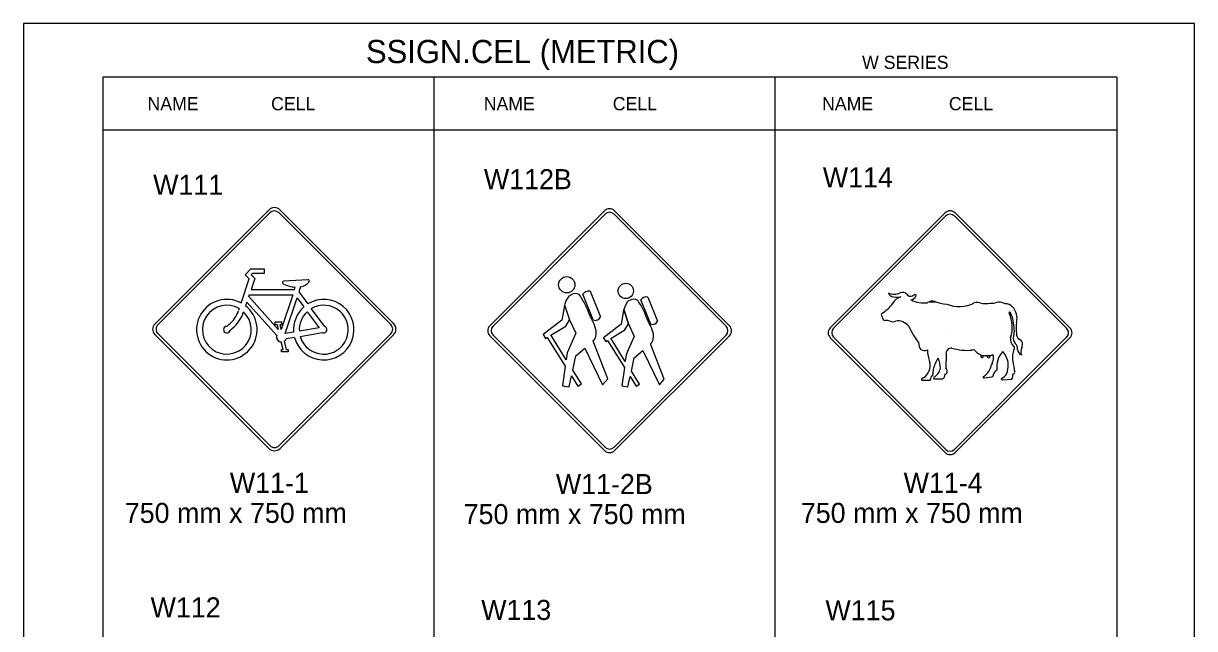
# Model space of a CAD drawing. Extents: x -12 to 6962, y -3756 to 679.
# Drawn here: x 2167.2 to 2342.4, y -112.9 to -22.3 of the extents above; entities that cross this region are included whole.
import ezdxf

# ---------------------------------------------------------------- set-up
doc = ezdxf.new("R2010")
doc.units = 0
for name, color, linetype in [('Level 1', 7, 'Continuous'), ('Level 2', 7, 'Continuous'), ('Level 3', 7, 'Continuous'), ('Level 62', 7, 'Continuous')]:
    doc.layers.add(name, color=color, linetype=linetype)

msp = doc.modelspace()

# ---------------------------------------------------------------- linework, layer by layer
at = {"layer": 'Level 1'}
for p, q in [((2330.8, -30.35), (2179.04, -30.35)), ((2179.04, -30.35), (2179.04, -230.35)), ((2228.56, -30.35), (2228.56, -230.35)), ((2279.62, -30.35), (2279.62, -230.35)), ((2330.8, -30.35), (2330.8, -230.35)), ((2330.8, -38.27), (2179.04, -38.27)), ((2186.83, -67.3), (2203.92, -50.21)), ((2187.31, -67.37), (2204.02, -50.67)), ((2205.44, -50.67), (2222.14, -67.37)), ((2205.54, -50.21), (2222.56, -67.23)), ((2236.95, -67.55), (2254.14, -50.37)), ((2255.63, -50.37), (2272.82, -67.55)), ((2287.91, -67.86), (2305.1, -50.67)), ((2306.59, -50.67), (2323.78, -67.86)), ((2237.45, -67.61), (2254.2, -50.86)), ((2255.57, -50.86), (2272.32, -67.61)), ((2288.41, -67.92), (2305.16, -51.17)), ((2306.53, -51.17), (2323.28, -67.92)), ((2200.33, -59.95), (2201.21, -59.06)), ((2201.21, -59.06), (2203.21, -59.06)), ((2203.21, -59.06), (2203.21, -59.73)), ((2199.74, -64.16), (2200.95, -60.56)), ((2200.95, -60.56), (2200.33, -59.95)), ((2201.78, -60.49), (2201.24, -62.13)), ((2201.5, -59.73), (2201.26, -59.95)), ((2201.26, -59.95), (2201.78, -60.49)), ((2203.21, -59.73), (2201.5, -59.73)), ((2206.14, -60.85), (2209.73, -60.66)), ((2200.88, -63.2), (2200.97, -62.92)), ((2200.97, -62.92), (2207.47, -62.92)), ((2201.24, -62.13), (2207.71, -62.13)), ((2207.47, -62.92), (2205.76, -68.11)), ((2207.71, -62.13), (2207.83, -61.75)), ((2208.63, -61.73), (2208.4, -62.47)), ((2208.4, -62.47), (2209.73, -64.28)), ((2252.43, -66.69), (2250.86, -62.85)), ((2251.96, -62.39), (2253.54, -66.24)), ((2200.59, -64.04), (2200.4, -64.58)), ((2205.07, -69.01), (2200.59, -64.04)), ((2205.3, -68.13), (2200.88, -63.2)), ((2206.35, -68.72), (2208.11, -63.37)), ((2208.11, -63.37), (2209.13, -64.73)), ((2248.14, -64.52), (2247.74, -66.73)), ((2248.16, -64.41), (2248.89, -66.65)), ((2261.04, -67.3), (2259.55, -63.68)), ((2260.59, -63.26), (2262.07, -66.88)), ((2302.77, -63.96), (2303.59, -63.96)), ((2199.47, -64.99), (2199.36, -65.3)), ((2200.07, -65.56), (2200.12, -65.46)), ((2209.63, -65.46), (2211.44, -67.87)), ((2212.25, -67.68), (2210.25, -64.99)), ((2256.99, -65.26), (2256.62, -67.33)), ((2257.7, -67.27), (2257.01, -65.15)), ((2257.01, -65.15), (2257.7, -67.27)), ((2197.93, -67.39), (2197.6, -67.65)), ((2198.1, -68.25), (2198.4, -67.99)), ((2204.72, -67.98), (2204.72, -67.98)), ((2205.83, -67.01), (2204.8, -67.01)), ((2204.8, -67.01), (2204.8, -67.37)), ((2204.8, -67.37), (2205.14, -67.37)), ((2205.14, -67.37), (2205.3, -68.13)), ((2205.76, -68.11), (2205.59, -67.37)), ((2205.59, -67.37), (2205.83, -67.37)), ((2205.83, -67.37), (2205.83, -67.01)), ((2211.44, -67.87), (2208.47, -68.37)), ((2248.34, -67.61), (2248.89, -66.65)), ((2248.89, -66.65), (2249.82, -68.67)), ((2254.9, -68.18), (2254.9, -68.18)), ((2257.18, -68.16), (2257.7, -67.27)), ((2257.7, -67.27), (2258.58, -69.16)), ((2261.03, -67.3), (2261.04, -67.3)), ((2203.88, -85.91), (2186.83, -68.86)), ((2204.02, -85.49), (2187.31, -68.79)), ((2222.14, -68.79), (2205.44, -85.49)), ((2222.56, -68.93), (2205.58, -85.91)), ((2206.02, -71.1), (2205.76, -69.99)), ((2206.18, -69.87), (2206.47, -71.1)), ((2207.59, -68.53), (2206.35, -68.72)), ((2207.73, -69.3), (2206.49, -69.51)), ((2208.59, -69.15), (2211.89, -68.58)), ((2254.14, -86.23), (2236.95, -69.05)), ((2254.2, -85.74), (2237.45, -68.98)), ((2244.93, -68.88), (2245.27, -69.48)), ((2245.56, -69.3), (2248.26, -73.61)), ((2248.4, -72.65), (2246.07, -68.94)), ((2253.98, -69.36), (2254.3, -69.92)), ((2254.58, -69.75), (2257.11, -73.8)), ((2257.24, -72.9), (2255.05, -69.41)), ((2272.32, -68.98), (2255.57, -85.74)), ((2272.82, -69.05), (2255.63, -86.23)), ((2305.1, -86.54), (2287.91, -69.35)), ((2305.16, -86.04), (2288.41, -69.29)), ((2305.86, -68.48), (2305.86, -68.48)), ((2323.28, -69.29), (2306.53, -86.04)), ((2323.78, -69.35), (2306.59, -86.54)), ((2205.78, -71.46), (2205.78, -71.1)), ((2205.78, -71.1), (2206.02, -71.1)), ((2206.8, -71.46), (2205.78, -71.46)), ((2206.47, -71.1), (2206.8, -71.1)), ((2206.8, -71.1), (2206.8, -71.46)), ((2249.82, -72.06), (2251.17, -70.92)), ((2258.58, -72.34), (2259.85, -71.27)), ((2305.23, -71.7), (2305.2, -73.84)), ((2310.4, -71.86), (2310.43, -72.18)), ((2310.41, -72.01), (2310.83, -72.01)), ((2310.83, -71.99), (2310.76, -72.2)), ((2310.93, -72.01), (2311.8, -72.01)), ((2311.41, -72.04), (2311.43, -72.22)), ((2311.81, -72), (2311.79, -72.21)), ((2249.17, -75.06), (2250.13, -76.6)), ((2250.66, -76.27), (2249.36, -74.19)), ((2257.97, -75.17), (2258.87, -76.61)), ((2259.37, -76.3), (2258.15, -74.35)), ((2302.93, -75.61), (2303.01, -75.24)), ((2303.32, -74.13), (2303.19, -75.04)), ((2305.01, -74.95), (2304.93, -75.31)), ((2310.93, -75.35), (2312.1, -75.2)), ((2247.84, -76.55), (2248.82, -76.69)), ((2250.13, -76.6), (2250.66, -76.27)), ((2256.71, -76.56), (2257.64, -76.7)), ((2258.87, -76.61), (2259.37, -76.3)), ((2301.57, -75.69), (2302.84, -75.69)), ((2303.39, -75.49), (2304.75, -75.49)), ((2313.66, -75.66), (2315.07, -75.57))]:
    msp.add_line(p, q, dxfattribs=at)
for points in [[(2250.38, -62.95), (2249.94, -62.73), (2249.43, -62.76), (2248.78, -63.13), (2248.41, -63.71), (2248.16, -64.41)], [(2259.1, -63.78), (2258.69, -63.57), (2258.21, -63.61), (2257.59, -63.95), (2257.25, -64.5), (2257.01, -65.15)], [(2247.74, -66.73), (2244.93, -68.88)], [(2246.1, -68.98), (2248.34, -67.61)], [(2256.62, -67.33), (2253.98, -69.36)], [(2255.08, -69.45), (2257.18, -68.16)], [(2245.27, -69.48), (2245.56, -69.3)], [(2249.82, -68.67), (2248.87, -70.82), (2248.55, -71.62), (2248.4, -72.65)], [(2251.17, -70.92), (2253.83, -76.4), (2254.6, -75.49), (2252.43, -69.86)], [(2254.3, -69.92), (2254.58, -69.75)], [(2258.58, -69.16), (2257.69, -71.18), (2257.38, -71.93), (2257.24, -72.9)], [(2259.85, -71.27), (2262.35, -76.42), (2263.07, -75.57), (2261.03, -70.28)], [(2248.26, -73.61), (2247.84, -76.55)], [(2249.36, -74.19), (2249.82, -72.06)], [(2258.15, -74.35), (2258.58, -72.34)], [(2248.82, -76.69), (2249.17, -75.06)], [(2257.11, -73.8), (2256.71, -76.56)], [(2257.64, -76.7), (2257.97, -75.17)]]:
    msp.add_lwpolyline(points, dxfattribs=at)
for centre, radius in [((2248.48, -61.43), 1.22), ((2257.31, -62.35), 1.15)]:
    msp.add_circle(centre, radius, dxfattribs=at)
for centre, radius, start, end in [((2204.73, -51.02), 1.15, 44.9996, 135), ((2204.73, -51.37), 1, 45.0004, 135), ((2254.88, -51.11), 1.06, 45, 135), ((2254.88, -51.55), 0.969, 45, 135), ((2305.84, -51.42), 1.06, 45, 135), ((2305.84, -51.85), 0.969, 45, 135), ((2206.15, -61.08), 0.219, 94.887, 243.2048), ((2208, -57.68), 4.09, 241.4742, 267.6541), ((2208.25, -59.59), 2.18, 280.5671, 319.1849), ((2209.73, -60.88), 0.22, 320.3575, 87.5675), ((2251.76, -63.48), 1.1, 79.5647, 144.9905), ((2297.48, -60.87), 1.97, 243.2991, 296.6897), ((2297.45, -62.35), 0.895, 198.167, 265.6654), ((2298.72, -63.42), 0.86, 41.3609, 114.2652), ((2299.91, -62.47), 0.665, 214.8516, 267.0314), ((2299.86, -62.12), 1.01, 271.0489, 307.1334), ((2300.58, -63.07), 0.179, 335.3908, 127.8661), ((2197.61, -68.14), 4.53, 61.7917, 51.9143), ((2197.6, -68.14), 3.66, 59.3986, 46.8616), ((2212.11, -68.15), 4.53, 131.1523, 184.8987), ((2212.11, -68.15), 4.53, 194.8442, 121.5006), ((2212.11, -68.15), 3.66, 196.0838, 120.3765), ((2260.4, -64.28), 1.04, 79.5647, 144.9905), ((2292.98, -61.14), 5.27, 300.7528, 324.5976), ((2298.96, -65.1), 1.92, 104.7013, 151.657), ((2297.92, -55.08), 8.19, 266.1894, 273.8892), ((2301.85, -60.13), 4.02, 242.3198, 278.6872), ((2299.79, -62.61), 1.09, 280.2814, 330.4086), ((2303.16, -65.2), 1.31, 72.8858, 122.5367), ((2306.09, -56.52), 7.85, 251.1122, 264.455), ((2307.17, -59.37), 5.3, 249.6739, 295.6743), ((2309.88, -65.67), 1.58, 68.3306, 105.1689), ((2311.19, -52.55), 11.67, 266.4272, 277.1491), ((2313.2, -65.87), 1.83, 60.6051, 107.7972), ((2314.19, -65.57), 1.29, 42.2532, 94.3591), ((2313.34, -66.45), 2.52, 345.3771, 43.9751), ((2194.93, -63.83), 4.65, 309.9442, 341.5047), ((2195.11, -63.96), 5.21, 309.3904, 342.0749), ((2212.03, -68.12), 3.58, 131.7888, 183.9783), ((2252.75, -65.89), 0.866, 248.7625, 335.7927), ((2295.76, -65.89), 0.237, 111.4509, 242.5309), ((2295.32, -66.39), 0.442, 347.9743, 41.657), ((2296.07, -66.46), 0.315, 183.9102, 296.2821), ((2314.77, -65.64), 0.102, 25.1865, 207.9729), ((2310.32, -67.76), 4.83, 341.0934, 25.3502), ((2309.4, -68.15), 6.04, 0.5587, 25.0529), ((2187.6, -68.08), 1.1, 135, 224.9996), ((2188.02, -68.08), 1, 135, 225.0002), ((2197.61, -68.14), 0.492, 91.5712, 347.2844), ((2212.11, -68.15), 0.484, 241.9191, 74.1835), ((2221.43, -68.08), 1, 315.0002, 45.0004), ((2221.71, -68.08), 1.2, 315, 44.9996), ((2237.7, -68.3), 1.06, 135, 225), ((2238.13, -68.3), 0.969, 135, 225), ((2261.33, -66.54), 0.814, 248.7625, 335.7927), ((2271.63, -68.3), 0.969, 315, 45), ((2272.07, -68.3), 1.06, 315, 45), ((2288.66, -68.6), 1.06, 135, 225), ((2289.09, -68.6), 0.969, 135, 225), ((2296.27, -68.05), 1.3, 63.4066, 92.7964), ((2297.24, -65.97), 0.987, 247.1212, 296.066), ((2297.99, -68.95), 2.12, 38.2743, 98.4599), ((2312.55, -61.58), 14.25, 205.1876, 216.8185), ((2313.48, -68.42), 1.98, 339.1736, 9.5378), ((2321.79, -67.92), 6.07, 172.0972, 187.9107), ((2322.6, -68.61), 0.969, 315, 45), ((2323.03, -68.61), 1.06, 315, 45), ((2205.8, -69.23), 0.757, 163.3345, 266.5441), ((2205.76, -69.18), 0.806, 301.8401, 335.167), ((2316.35, -69.54), 1.48, 171.6729, 226.4115), ((2316.49, -69.42), 1.2, 165.9956, 221.2182), ((2316.77, -68.77), 0.996, 178.9162, 232.2411), ((2315.83, -70.36), 0.869, 328.271, 67.6706), ((2302.47, -70.21), 1.34, 176.0043, 222.0407), ((2302.01, -70.39), 0.889, 233.1494, 301.637), ((2306.93, -71.31), 4.46, 177.919, 202.2598), ((2306.06, -71.74), 0.837, 86.593, 177.2212), ((2308.51, -62.65), 8.59, 253.8294, 274.1086), ((2309.31, -71.57), 0.401, 64.834, 118.7332), ((2311.34, -69.56), 2.49, 221.6207, 247.7561), ((2316.17, -73.7), 3.36, 136.797, 188.5756), ((2311.22, -73.62), 3.34, 4.9286, 41.5509), ((2318.51, -72.35), 3.34, 157.2094, 189.4128), ((2315.21, -70.87), 0.292, 319.8105, 65.5599), ((2315.04, -70.94), 0.913, 347.8419, 52.7972), ((2317, -70.97), 1.08, 188.1892, 243.1821), ((2317.79, -71.44), 1.36, 152.9854, 201.1756), ((2300.63, -73.49), 2.23, 303.8764, 12.7096), ((2308.78, -75.33), 5.59, 148.5923, 167.5611), ((2301.72, -73.78), 2.67, 356.3269, 30.5067), ((2310.6, -72.15), 0.174, 191.7912, 343.222), ((2311.34, -69.56), 2.49, 258.1965, 271.4772), ((2311.61, -72.16), 0.191, 199.2718, 344.2955), ((2314.97, -74.74), 3.24, 149.9214, 168.0346), ((2311.34, -69.56), 2.49, 280.731, 290.9796), ((2310.94, -72.43), 1.4, 330.7096, 23.1968), ((2309.82, -73.28), 4.73, 342.1562, 359.372), ((2381.37, -61.84), 67.06, 189.4926, 190.8133), ((2301.9, -75.67), 0.332, 94.2755, 183.6166), ((2303.31, -75.32), 0.308, 112.9225, 164.6031), ((2303.52, -75.4), 0.159, 127.558, 214.4682), ((2302.35, -73.48), 2.09, 300.7854, 346.7542), ((2304.6, -75.15), 0.374, 294.5918, 333.7182), ((2305.19, -74.97), 0.185, 108.6977, 174.9841), ((2305.08, -74.48), 0.322, 280.4568, 6.3888), ((2304.45, -74.42), 0.949, 358.3369, 37.2222), ((2310.91, -75.23), 0.119, 133.525, 279.5531), ((2309.96, -73.39), 1.96, 296.0822, 339.6102), ((2311.98, -74.92), 0.304, 293.3764, 346.2014), ((2312.87, -75.04), 0.593, 153.1881, 175.4544), ((2313.51, -75.31), 1.29, 120.8123, 155.0312), ((2312.73, -73.77), 1.86, 295.0895, 328.9824), ((2314.16, -74.98), 1.08, 327.1815, 9.2056), ((2315.23, -74.52), 0.284, 270.7579, 21.0787), ((2302.78, -75.54), 0.168, 290.6537, 332.4752), ((2313.64, -75.52), 0.139, 150.8745, 280.7866), ((2204.73, -84.78), 1, 225.0002, 315.0002), ((2254.88, -85.05), 0.969, 225, 315), ((2204.73, -85.06), 1.2, 224.9996, 315), ((2254.88, -85.49), 1.06, 225, 315), ((2305.84, -85.79), 1.06, 225, 315), ((2305.84, -85.36), 0.969, 225, 315)]:
    msp.add_arc(centre, radius, start, end, dxfattribs=at)
for points in [[(2252.43, -69.86), (2252.76, -69.35), (2252.87, -68.3), (2252.41, -67), (2251.86, -65.85), (2251.35, -64.6), (2250.38, -62.95)], [(2261.03, -70.28), (2261.34, -69.8), (2261.44, -68.81), (2261.01, -67.58), (2260.49, -66.5), (2260.02, -65.33), (2259.1, -63.78)]]:
    msp.add_spline(points, degree=3, dxfattribs=at)
at = {"layer": 'Level 62'}
msp.add_lwpolyline([(2167.17, -235.4), (2342.43, -235.4), (2342.43, -22.31), (2167.17, -22.31)], close=True, dxfattribs=at)

# ---------------------------------------------------------------- texts
at = {"layer": 'Level 2'}
for s, p in [('W111', (2186.58, -47.96)), ('W112B', (2236.08, -47.12)), ('W114', (2286.8, -46.85)), ('W112', (2186.2, -111.21)), ('W113', (2235.67, -111.59)), ('W115', (2287.19, -111.65))]:
    msp.add_text(s, height=3, dxfattribs=at).set_placement(p)
at = {"layer": 'Level 3'}
for s, height, p in [('SSIGN.CEL (METRIC)', 3.4642, (2218.43, -28.24)), ('W SERIES', 1.979, (2292.67, -29.12)), ('NAME', 1.98, (2185.73, -35.31)), ('CELL', 1.98, (2204.23, -35.31)), ('NAME', 1.98, (2236.05, -35.31)), ('CELL', 1.98, (2255.36, -35.31)), ('NAME', 1.98, (2286.68, -35.31)), ('CELL', 1.98, (2305.66, -35.31)), ('W11-1', 3, (2198.06, -92.57)), ('W11-2B', 3, (2246.85, -92.75)), ('W11-4', 3, (2298.89, -92.57)), ('750 mm x 750 mm', 3, (2182.34, -97.07)), ('750 mm x 750 mm', 3, (2233.05, -97.25)), ('750 mm x 750 mm', 3, (2283.51, -97.07))]:
    msp.add_text(s, height=height, dxfattribs=at).set_placement(p)

doc.saveas('drawing.dxf')
